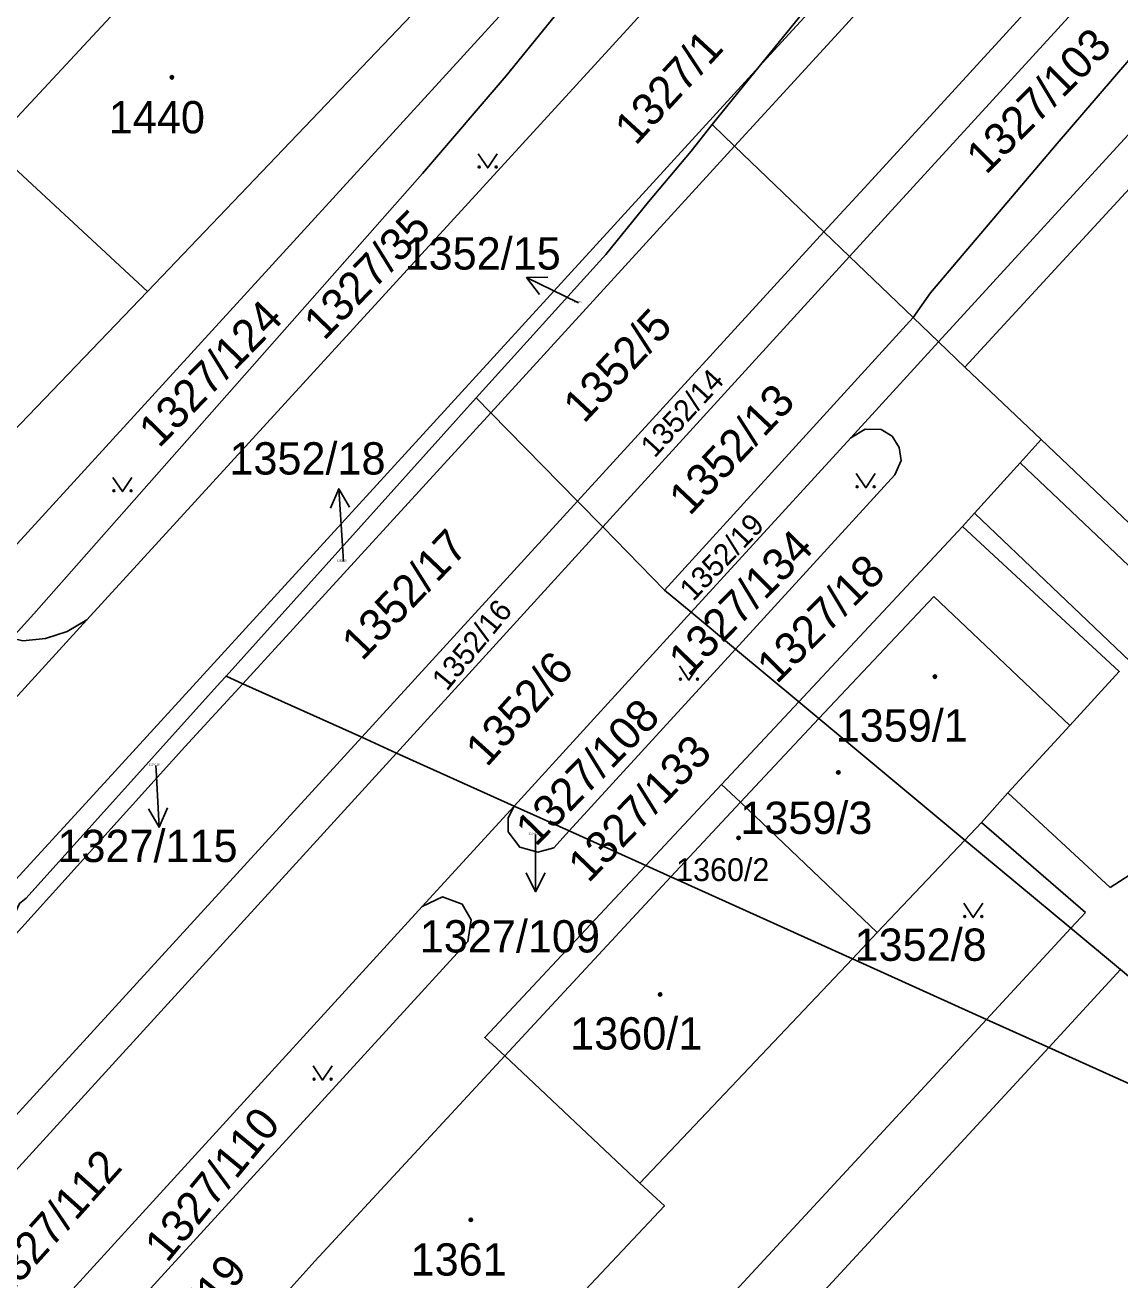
# Model space of a CAD drawing. Extents: x -598934 to -598196, y -1162208 to -1161502.
# Drawn here: x -598541.5 to -598483.9, y -1161724.5 to -1161658.4 of the extents above; entities that cross this region are included whole.
import ezdxf

# ---------------------------------------------------------------- set-up
doc = ezdxf.new("R2010")
doc.units = 0
for name, color, linetype in [('KN_CAR_KR', 7, 'Continuous'), ('KN_KULTURY', 7, 'Continuous'), ('KN_PARC_CIS_POM', 7, 'Continuous'), ('KN_PARC_CIS_POZ', 7, 'Continuous'), ('KN_PARC_CIS_STAV', 7, 'Continuous'), ('KN_PARC_PLOCHA', 7, 'Continuous'), ('PARC_C_SIPKA', 7, 'Continuous'), ('parcely_l', 7, 'Continuous')]:
    doc.layers.add(name, color=color, linetype=linetype)

msp = doc.modelspace()

# ---------------------------------------------------------------- linework, layer by layer
at = {"layer": 'KN_CAR_KR'}
for points in [[(-598489.16, -1161681.44), (-598464.99, -1161704.34)], [(-598491.55, -1161684.09), (-598483.38, -1161691.88)], [(-598499.74, -1161694.9), (-598493.7, -1161688.48)], [(-598493.7, -1161688.48), (-598486.54, -1161695.27)], [(-598503.87, -1161699.3), (-598499.74, -1161694.9)], [(-598503.87, -1161699.3), (-598507.53, -1161703.24)], [(-598484.42, -1161703.8), (-598489.8, -1161698.81)], [(-598491.18, -1161700.37), (-598485.72, -1161705.11)], [(-598507.53, -1161703.24), (-598516.27, -1161712.67)], [(-598484.42, -1161703.8), (-598482.89, -1161702.81)], [(-598485.72, -1161705.11), (-598486.49, -1161705.94)], [(-598486.49, -1161705.94), (-598490.92, -1161710.74)], [(-598487.64, -1161712.22), (-598483.87, -1161708.12)], [(-598490.92, -1161710.74), (-598521.91, -1161744.24)], [(-598499.66, -1161725.25), (-598487.64, -1161712.22)]]:
    msp.add_lwpolyline(points, dxfattribs=at)
at = {"layer": 'KN_KULTURY'}
for points in [[(-598517.672, -1161665.172), (-598517.172, -1161665.922), (-598516.672, -1161665.172)], [(-598536.892, -1161682.212), (-598536.392, -1161682.962), (-598535.892, -1161682.212)], [(-598497.782, -1161682.002), (-598497.282, -1161682.752), (-598496.782, -1161682.002)], [(-598507.082, -1161692.132), (-598506.582, -1161692.882), (-598506.082, -1161692.132)], [(-598492.122, -1161704.632), (-598491.622, -1161705.382), (-598491.122, -1161704.632)], [(-598526.362, -1161713.192), (-598525.862, -1161713.942), (-598525.362, -1161713.192)]]:
    msp.add_lwpolyline(points, dxfattribs=at)
for centre, radius in [((-598533.79, -1161661.15), 0.09), ((-598533.79, -1161661.15), 0.0398), ((-598517.622, -1161665.871), 0.05), ((-598516.723, -1161665.871), 0.05), ((-598536.842, -1161682.911), 0.05), ((-598535.943, -1161682.911), 0.05), ((-598497.732, -1161682.701), 0.05), ((-598496.833, -1161682.701), 0.05), ((-598507.032, -1161692.831), 0.05), ((-598506.133, -1161692.831), 0.05), ((-598493.64, -1161692.7), 0.09), ((-598493.64, -1161692.7), 0.0398), ((-598498.72, -1161697.74), 0.09), ((-598498.72, -1161697.74), 0.0398), ((-598503.97, -1161701.19), 0.09), ((-598503.97, -1161701.19), 0.0398), ((-598492.072, -1161705.331), 0.05), ((-598491.173, -1161705.331), 0.05), ((-598508.1, -1161709.43), 0.09), ((-598508.1, -1161709.43), 0.0398), ((-598526.312, -1161713.891), 0.05), ((-598525.413, -1161713.891), 0.05), ((-598518.06, -1161721.29), 0.09), ((-598518.06, -1161721.29), 0.0398)]:
    msp.add_circle(centre, radius, dxfattribs=at)
at = {"layer": 'KN_PARC_PLOCHA'}
for points in [[(-598601.64, -1161758.47), (-598594.41, -1161746.34), (-598574.71, -1161725.04), (-598562.49, -1161716.2), (-598546.26, -1161698.46), (-598538.27, -1161689.71), (-598508.71, -1161657.4), (-598500.6, -1161648.49), (-598493.91, -1161641.2), (-598488.42, -1161635.24), (-598481.9, -1161628.09), (-598472.12, -1161617.39), (-598454.81, -1161598.51), (-598446.33, -1161589.22), (-598435.01, -1161576.84), (-598438.32, -1161581.74), (-598452.8, -1161599.01), (-598453, -1161599.23), (-598502.88, -1161660.58), (-598537.16, -1161698.1), (-598569.06, -1161732.86), (-598601.28, -1161767.71)], [(-598444.82, -1161773.72), (-598474.53, -1161747.01), (-598458.77, -1161729.49), (-598468.63, -1161720.8), (-598458.45, -1161708.36), (-598488.05, -1161680.21), (-598492.06, -1161676.4), (-598438.63, -1161618.4)], [(-598510.61, -1161651.4), (-598544.94, -1161688.98), (-598543.81, -1161690.01), (-598542.71, -1161690.57), (-598542.22, -1161690.68), (-598545.81, -1161694.66), (-598546.28, -1161693.77), (-598547.91, -1161692.23), (-598565.2, -1161711.02), (-598575.32, -1161722.3), (-598575.72, -1161723.15), (-598605.82, -1161757.29)], [(-598600.45, -1161744.8), (-598587.23, -1161729.92), (-598586.27, -1161722.54), (-598585.47, -1161716.45), (-598581.89, -1161716.57), (-598581.96, -1161717.66), (-598579.95, -1161717.69), (-598579.94, -1161716.62), (-598578.57, -1161716.67), (-598576.31, -1161714.19), (-598575.54, -1161714.86), (-598573.24, -1161712.35), (-598573.97, -1161711.71), (-598571.95, -1161709.54), (-598560.12, -1161696.91), (-598552.08, -1161688.35), (-598548.99, -1161685.08), (-598548.07, -1161684.17), (-598547.19, -1161685.05), (-598535.07, -1161672.42), (-598520.79, -1161657.48)], [(-598538.31, -1161728.62), (-598518.22, -1161706.64), (-598518.05, -1161705.51), (-598518.51, -1161704.67), (-598519.56, -1161704.29), (-598520.62, -1161704.8), (-598515.78, -1161699.51), (-598516.09, -1161700.14), (-598516.1, -1161700.87), (-598515.49, -1161701.68), (-598514.54, -1161701.94), (-598513.69, -1161701.71), (-598512.88, -1161700.82), (-598508.86, -1161702.64), (-598510.5, -1161704.39), (-598517.33, -1161711.7), (-598516.27, -1161712.67), (-598526.27, -1161723.47), (-598528.95, -1161726.46)]]:
    msp.add_lwpolyline(points, dxfattribs=at)
for points in [[(-598449.39, -1161602.22), (-598457.13, -1161610.69), (-598502.88, -1161660.58), (-598453, -1161599.23), (-598452.8, -1161599.01)], [(-598447.76, -1161603.75), (-598454.84, -1161611.48), (-598455.16, -1161611.23), (-598501.41, -1161661.76), (-598504.18, -1161664.78), (-598505.37, -1161663.64), (-598502.88, -1161660.58), (-598457.13, -1161610.69), (-598449.39, -1161602.22)], [(-598443.61, -1161607.65), (-598450.63, -1161615.3), (-598450.33, -1161615.61), (-598497.15, -1161666.75), (-598499.48, -1161669.29), (-598504.18, -1161664.78), (-598501.41, -1161661.76), (-598455.16, -1161611.23), (-598454.84, -1161611.48), (-598447.76, -1161603.75)], [(-598441.98, -1161609.19), (-598452.99, -1161621.22), (-598496.1, -1161668.36), (-598498.13, -1161670.59), (-598499.48, -1161669.29), (-598497.15, -1161666.75), (-598450.33, -1161615.61), (-598450.63, -1161615.3), (-598443.61, -1161607.65)], [(-598440.63, -1161610.45), (-598487.2, -1161664.63), (-598493.87, -1161672.5), (-598494.79, -1161673.79), (-598498.13, -1161670.59), (-598496.1, -1161668.36), (-598452.99, -1161621.22), (-598441.98, -1161609.19)], [(-598437.32, -1161613.76), (-598448.19, -1161625.65), (-598493.45, -1161675.07), (-598494.79, -1161673.79), (-598493.87, -1161672.5), (-598487.2, -1161664.63), (-598440.63, -1161610.45), (-598440.23, -1161610.79), (-598438.3, -1161612.74)], [(-598435.81, -1161615.34), (-598438.63, -1161618.4), (-598492.06, -1161676.4), (-598493.45, -1161675.07), (-598448.19, -1161625.65), (-598437.32, -1161613.76)], [(-598509.32, -1161652.6), (-598516.2, -1161661.08), (-598520.6, -1161666.22), (-598541.05, -1161689.39), (-598542.22, -1161690.68), (-598542.71, -1161690.57), (-598543.81, -1161690.01), (-598544.94, -1161688.98), (-598510.61, -1161651.4)], [(-598508.71, -1161657.4), (-598538.27, -1161689.71), (-598539.31, -1161690.33), (-598540.45, -1161690.7), (-598541.63, -1161690.81), (-598542.22, -1161690.68), (-598541.05, -1161689.39), (-598520.6, -1161666.22), (-598516.2, -1161661.08), (-598509.32, -1161652.6), (-598508.82, -1161653.06), (-598508.32, -1161653.87), (-598508.03, -1161654.99), (-598508.15, -1161656.06)], [(-598520.79, -1161657.48), (-598535.07, -1161672.42), (-598543.36, -1161664.75), (-598536.1, -1161656.95), (-598533.57, -1161654.46), (-598530.26, -1161654.98), (-598526.88, -1161655.45), (-598523.54, -1161655.94)], [(-598536.1, -1161656.95), (-598543.36, -1161664.75), (-598548.22, -1161669.81), (-598553.01, -1161665.26), (-598553.29, -1161665.01), (-598553.46, -1161664.69), (-598553.52, -1161664.38), (-598553.45, -1161663.96), (-598553.24, -1161663.61), (-598552.96, -1161663.37), (-598548.13, -1161658.38), (-598545.02, -1161655.24), (-598536.87, -1161656.25)], [(-598505.37, -1161663.64), (-598506.47, -1161665.03), (-598508.71, -1161667.7), (-598510.96, -1161670.48), (-598517.78, -1161678.03), (-598530.94, -1161692.67), (-598531.26, -1161693.01), (-598541.47, -1161704.37), (-598541.81, -1161704.64), (-598543.16, -1161707.52), (-598568.17, -1161734.75), (-598580.79, -1161748.69), (-598599.26, -1161769.56), (-598615.93, -1161788.89), (-598618.28, -1161786.85), (-598601.28, -1161767.71), (-598569.06, -1161732.86), (-598537.16, -1161698.1), (-598502.88, -1161660.58)], [(-598504.18, -1161664.78), (-598517.01, -1161678.81), (-598517.78, -1161678.03), (-598510.96, -1161670.48), (-598508.71, -1161667.7), (-598506.47, -1161665.03), (-598505.37, -1161663.64)], [(-598535.07, -1161672.42), (-598547.19, -1161685.05), (-598548.07, -1161684.17), (-598555.37, -1161677.21), (-598550.02, -1161671.6), (-598548.22, -1161669.81), (-598543.36, -1161664.75)], [(-598499.48, -1161669.29), (-598512.45, -1161683.47), (-598517.01, -1161678.81), (-598504.18, -1161664.78)], [(-598498.13, -1161670.59), (-598511.12, -1161684.82), (-598512.45, -1161683.47), (-598499.48, -1161669.29)], [(-598494.79, -1161673.79), (-598507.87, -1161688.14), (-598511.12, -1161684.82), (-598498.13, -1161670.59)], [(-598493.45, -1161675.07), (-598498.07, -1161680.12), (-598506.46, -1161689.31), (-598507.87, -1161688.14), (-598494.79, -1161673.79)], [(-598492.06, -1161676.4), (-598488.05, -1161680.21), (-598489.16, -1161681.44), (-598491.55, -1161684.09), (-598492.18, -1161684.79), (-598500.8, -1161694.02), (-598504.13, -1161691.25), (-598495.74, -1161682.07), (-598495.42, -1161681.32), (-598495.52, -1161680.63), (-598495.89, -1161680.04), (-598496.47, -1161679.69), (-598497.31, -1161679.68), (-598498.07, -1161680.12), (-598493.45, -1161675.07)], [(-598517.01, -1161678.81), (-598530.06, -1161693.07), (-598530.94, -1161692.67), (-598517.78, -1161678.03)], [(-598512.45, -1161683.47), (-598523.8, -1161695.89), (-598530.06, -1161693.07), (-598517.01, -1161678.81)], [(-598504.13, -1161691.25), (-598506.46, -1161689.31), (-598498.07, -1161680.12), (-598497.31, -1161679.68), (-598496.47, -1161679.69), (-598495.89, -1161680.04), (-598495.52, -1161680.63), (-598495.42, -1161681.32), (-598495.74, -1161682.07)], [(-598468.63, -1161720.8), (-598471.86, -1161718.12), (-598473.6, -1161716.67), (-598483.87, -1161708.12), (-598486.49, -1161705.94), (-598492.06, -1161701.3), (-598491.18, -1161700.37), (-598489.8, -1161698.81), (-598486.54, -1161695.27), (-598483.94, -1161692.43), (-598492.18, -1161684.79), (-598491.55, -1161684.09), (-598489.16, -1161681.44), (-598488.05, -1161680.21), (-598458.45, -1161708.36)], [(-598511.12, -1161684.82), (-598521.97, -1161696.72), (-598523.8, -1161695.89), (-598512.45, -1161683.47)], [(-598507.87, -1161688.14), (-598506.46, -1161689.31), (-598515.78, -1161699.51), (-598521.97, -1161696.72), (-598511.12, -1161684.82)], [(-598492.06, -1161701.3), (-598499.74, -1161694.9), (-598500.8, -1161694.02), (-598492.18, -1161684.79), (-598483.94, -1161692.43), (-598486.54, -1161695.27), (-598489.8, -1161698.81), (-598491.18, -1161700.37)], [(-598504.13, -1161691.25), (-598512.88, -1161700.82), (-598515.78, -1161699.51), (-598506.46, -1161689.31)], [(-598546.26, -1161698.46), (-598545.63, -1161697.5), (-598545.35, -1161696.46), (-598545.49, -1161695.27), (-598545.81, -1161694.66), (-598542.22, -1161690.68), (-598541.63, -1161690.81), (-598540.45, -1161690.7), (-598539.31, -1161690.33), (-598538.27, -1161689.71)], [(-598500.8, -1161694.02), (-598504.87, -1161698.37), (-598508.86, -1161702.64), (-598512.88, -1161700.82), (-598504.13, -1161691.25)], [(-598530.06, -1161693.07), (-598533.11, -1161696.4), (-598543.16, -1161707.52), (-598541.81, -1161704.64), (-598541.47, -1161704.37), (-598531.26, -1161693.01), (-598530.94, -1161692.67)], [(-598523.8, -1161695.89), (-598544.3, -1161718.3), (-598568.94, -1161745.33), (-598571.83, -1161742.74), (-598572.86, -1161741.8), (-598567.54, -1161735.78), (-598565.39, -1161733.07), (-598543.16, -1161707.52), (-598533.11, -1161696.4), (-598530.06, -1161693.07)], [(-598492.06, -1161701.3), (-598496.67, -1161706.17), (-598503.87, -1161699.3), (-598504.87, -1161698.37), (-598500.8, -1161694.02), (-598499.74, -1161694.9)], [(-598521.97, -1161696.72), (-598547.88, -1161725.12), (-598567, -1161747.08), (-598568.94, -1161745.33), (-598544.3, -1161718.3), (-598523.8, -1161695.89)], [(-598515.78, -1161699.51), (-598520.62, -1161704.8), (-598540.3, -1161726.37), (-598545.62, -1161732.34), (-598551.22, -1161738.78), (-598552.06, -1161740.1), (-598557.21, -1161749.89), (-598557.79, -1161750.75), (-598560.03, -1161753.34), (-598567, -1161747.08), (-598547.88, -1161725.12), (-598521.97, -1161696.72)], [(-598496.67, -1161706.17), (-598497.98, -1161707.55), (-598507.53, -1161703.24), (-598508.86, -1161702.64), (-598504.87, -1161698.37), (-598503.87, -1161699.3)], [(-598512.88, -1161700.82), (-598513.69, -1161701.71), (-598514.54, -1161701.94), (-598515.49, -1161701.68), (-598516.1, -1161700.87), (-598516.09, -1161700.14), (-598515.78, -1161699.51)], [(-598468.63, -1161720.8), (-598472.67, -1161718.98), (-598474.84, -1161718), (-598487.64, -1161712.22), (-598490.92, -1161710.74), (-598497.98, -1161707.55), (-598496.67, -1161706.17), (-598492.06, -1161701.3), (-598486.49, -1161705.94), (-598483.87, -1161708.12), (-598473.6, -1161716.67), (-598471.86, -1161718.12)], [(-598497.98, -1161707.55), (-598509.16, -1161719.36), (-598516.27, -1161712.67), (-598517.33, -1161711.7), (-598510.5, -1161704.39), (-598508.86, -1161702.64), (-598507.53, -1161703.24)], [(-598540.3, -1161726.37), (-598520.62, -1161704.8), (-598519.56, -1161704.29), (-598518.51, -1161704.67), (-598518.05, -1161705.51), (-598518.22, -1161706.64), (-598538.31, -1161728.62), (-598539.25, -1161728.86), (-598540.1, -1161728.5), (-598540.65, -1161727.46)], [(-598468.63, -1161720.8), (-598458.77, -1161729.49), (-598474.53, -1161747.01), (-598505.54, -1161780.43), (-598505.91, -1161780.84), (-598507.88, -1161780.28), (-598515.19, -1161778.23), (-598542.18, -1161767.07), (-598540.95, -1161765.46), (-598543.04, -1161763.56), (-598545.78, -1161761.07), (-598536.13, -1161750.75), (-598533.19, -1161747.65), (-598527.64, -1161741.82), (-598526.22, -1161740.28), (-598520.88, -1161734.41), (-598507.87, -1161720.56), (-598509.16, -1161719.36), (-598497.98, -1161707.55), (-598490.92, -1161710.74), (-598487.64, -1161712.22), (-598474.84, -1161718), (-598472.67, -1161718.98)], [(-598509.16, -1161719.36), (-598507.87, -1161720.56), (-598520.88, -1161734.41), (-598528.95, -1161726.46), (-598526.27, -1161723.47), (-598516.27, -1161712.67)]]:
    msp.add_lwpolyline(points, close=True, dxfattribs=at)
at = {"layer": 'PARC_C_SIPKA'}
for points in [[(-598514.448, -1161672.576), (-598515.129, -1161671.69), (-598514.011, -1161671.677)], [(-598512.39, -1161673.02), (-598512.43, -1161673), (-598515.129, -1161671.69)], [(-598525.449, -1161683.837), (-598525.015, -1161682.806), (-598524.451, -1161683.772)], [(-598524.77, -1161686.64), (-598524.82, -1161685.8), (-598525.015, -1161682.806)], [(-598534.63, -1161697.38), (-598534.62, -1161697.63), (-598534.467, -1161700.626)], [(-598534.019, -1161699.602), (-598534.467, -1161700.626), (-598535.017, -1161699.653)], [(-598514.65, -1161701.01), (-598514.65, -1161701.02), (-598514.65, -1161704.02)], [(-598514.15, -1161703.02), (-598514.65, -1161704.02), (-598515.15, -1161703.02)]]:
    msp.add_lwpolyline(points, dxfattribs=at)
at = {"layer": 'parcely_l'}
for points in [[(-598502.88, -1161660.58), (-598453, -1161599.23), (-598452.8, -1161599.01)], [(-598449.39, -1161602.22), (-598457.13, -1161610.69), (-598502.88, -1161660.58)], [(-598504.18, -1161664.78), (-598501.41, -1161661.76), (-598455.16, -1161611.23), (-598454.84, -1161611.48), (-598447.76, -1161603.75)], [(-598443.61, -1161607.65), (-598450.63, -1161615.3), (-598450.33, -1161615.61), (-598497.15, -1161666.75), (-598499.48, -1161669.29)], [(-598498.13, -1161670.59), (-598496.1, -1161668.36), (-598452.99, -1161621.22), (-598441.98, -1161609.19)], [(-598440.63, -1161610.45), (-598487.2, -1161664.63), (-598493.87, -1161672.5), (-598494.79, -1161673.79)], [(-598493.45, -1161675.07), (-598448.19, -1161625.65), (-598437.32, -1161613.76)], [(-598435.81, -1161615.34), (-598438.63, -1161618.4), (-598492.06, -1161676.4)], [(-598510.61, -1161651.4), (-598544.94, -1161688.98), (-598543.81, -1161690.01), (-598542.71, -1161690.57), (-598542.22, -1161690.68)], [(-598542.22, -1161690.68), (-598541.05, -1161689.39), (-598520.6, -1161666.22), (-598516.2, -1161661.08), (-598509.32, -1161652.6)], [(-598543.36, -1161664.75), (-598536.1, -1161656.95)], [(-598508.71, -1161657.4), (-598538.27, -1161689.71)], [(-598520.79, -1161657.48), (-598535.07, -1161672.42)], [(-598618.28, -1161786.85), (-598601.28, -1161767.71), (-598569.06, -1161732.86), (-598537.16, -1161698.1), (-598502.88, -1161660.58)], [(-598502.88, -1161660.58), (-598505.37, -1161663.64)], [(-598517.78, -1161678.03), (-598510.96, -1161670.48), (-598508.71, -1161667.7), (-598506.47, -1161665.03), (-598505.37, -1161663.64)], [(-598505.37, -1161663.64), (-598504.18, -1161664.78)], [(-598543.36, -1161664.75), (-598535.07, -1161672.42)], [(-598504.18, -1161664.78), (-598517.01, -1161678.81)], [(-598504.18, -1161664.78), (-598499.48, -1161669.29)], [(-598499.48, -1161669.29), (-598512.45, -1161683.47)], [(-598499.48, -1161669.29), (-598498.13, -1161670.59)], [(-598511.12, -1161684.82), (-598498.13, -1161670.59)], [(-598494.79, -1161673.79), (-598498.13, -1161670.59)], [(-598535.07, -1161672.42), (-598547.19, -1161685.05), (-598548.07, -1161684.17)], [(-598494.79, -1161673.79), (-598507.87, -1161688.14)], [(-598493.45, -1161675.07), (-598494.79, -1161673.79)], [(-598493.45, -1161675.07), (-598498.07, -1161680.12)], [(-598492.06, -1161676.4), (-598493.45, -1161675.07)], [(-598492.06, -1161676.4), (-598488.05, -1161680.21)], [(-598530.94, -1161692.67), (-598517.78, -1161678.03)], [(-598517.78, -1161678.03), (-598517.01, -1161678.81)], [(-598517.01, -1161678.81), (-598530.06, -1161693.07)], [(-598512.45, -1161683.47), (-598517.01, -1161678.81)], [(-598498.07, -1161680.12), (-598506.46, -1161689.31)], [(-598498.07, -1161680.12), (-598497.31, -1161679.68), (-598496.47, -1161679.69), (-598495.89, -1161680.04), (-598495.52, -1161680.63), (-598495.42, -1161681.32), (-598495.74, -1161682.07), (-598504.13, -1161691.25)], [(-598492.18, -1161684.79), (-598491.55, -1161684.09), (-598489.16, -1161681.44), (-598488.05, -1161680.21)], [(-598488.05, -1161680.21), (-598458.45, -1161708.36), (-598468.63, -1161720.8)], [(-598512.45, -1161683.47), (-598523.8, -1161695.89)], [(-598512.45, -1161683.47), (-598511.12, -1161684.82)], [(-598511.12, -1161684.82), (-598521.97, -1161696.72)], [(-598507.87, -1161688.14), (-598511.12, -1161684.82)], [(-598500.8, -1161694.02), (-598492.18, -1161684.79)], [(-598492.06, -1161701.3), (-598491.18, -1161700.37), (-598489.8, -1161698.81), (-598486.54, -1161695.27), (-598483.94, -1161692.43), (-598492.18, -1161684.79)], [(-598506.46, -1161689.31), (-598507.87, -1161688.14)], [(-598515.78, -1161699.51), (-598506.46, -1161689.31)], [(-598506.46, -1161689.31), (-598504.13, -1161691.25)], [(-598538.27, -1161689.71), (-598546.26, -1161698.46)], [(-598538.27, -1161689.71), (-598539.31, -1161690.33), (-598540.45, -1161690.7), (-598541.63, -1161690.81), (-598542.22, -1161690.68)], [(-598504.13, -1161691.25), (-598512.88, -1161700.82)], [(-598504.13, -1161691.25), (-598500.8, -1161694.02)], [(-598530.94, -1161692.67), (-598531.26, -1161693.01), (-598541.47, -1161704.37), (-598541.81, -1161704.64), (-598543.16, -1161707.52)], [(-598530.06, -1161693.07), (-598530.94, -1161692.67)], [(-598530.06, -1161693.07), (-598533.11, -1161696.4), (-598543.16, -1161707.52)], [(-598523.8, -1161695.89), (-598530.06, -1161693.07)], [(-598504.87, -1161698.37), (-598500.8, -1161694.02)], [(-598500.8, -1161694.02), (-598499.74, -1161694.9), (-598492.06, -1161701.3)], [(-598523.8, -1161695.89), (-598544.3, -1161718.3), (-598568.94, -1161745.33)], [(-598521.97, -1161696.72), (-598523.8, -1161695.89)], [(-598521.97, -1161696.72), (-598547.88, -1161725.12), (-598567, -1161747.08)], [(-598515.78, -1161699.51), (-598521.97, -1161696.72)], [(-598508.86, -1161702.64), (-598504.87, -1161698.37)], [(-598496.67, -1161706.17), (-598503.87, -1161699.3), (-598504.87, -1161698.37)], [(-598520.62, -1161704.8), (-598515.78, -1161699.51)], [(-598512.88, -1161700.82), (-598513.69, -1161701.71), (-598514.54, -1161701.94), (-598515.49, -1161701.68), (-598516.1, -1161700.87), (-598516.09, -1161700.14), (-598515.78, -1161699.51)], [(-598512.88, -1161700.82), (-598515.78, -1161699.51)], [(-598508.86, -1161702.64), (-598512.88, -1161700.82)], [(-598492.06, -1161701.3), (-598496.67, -1161706.17)], [(-598468.63, -1161720.8), (-598471.86, -1161718.12), (-598473.6, -1161716.67), (-598483.87, -1161708.12), (-598486.49, -1161705.94), (-598492.06, -1161701.3)], [(-598516.27, -1161712.67), (-598517.33, -1161711.7), (-598510.5, -1161704.39), (-598508.86, -1161702.64)], [(-598508.86, -1161702.64), (-598507.53, -1161703.24), (-598497.98, -1161707.55)], [(-598520.62, -1161704.8), (-598519.56, -1161704.29), (-598518.51, -1161704.67), (-598518.05, -1161705.51), (-598518.22, -1161706.64), (-598538.31, -1161728.62), (-598539.25, -1161728.86), (-598540.1, -1161728.5), (-598540.65, -1161727.46), (-598540.3, -1161726.37)], [(-598540.3, -1161726.37), (-598520.62, -1161704.8)], [(-598496.67, -1161706.17), (-598497.98, -1161707.55)], [(-598497.98, -1161707.55), (-598509.16, -1161719.36)], [(-598468.63, -1161720.8), (-598472.67, -1161718.98), (-598474.84, -1161718), (-598487.64, -1161712.22), (-598490.92, -1161710.74), (-598497.98, -1161707.55)], [(-598528.95, -1161726.46), (-598526.27, -1161723.47), (-598516.27, -1161712.67)], [(-598516.27, -1161712.67), (-598509.16, -1161719.36)], [(-598509.16, -1161719.36), (-598507.87, -1161720.56), (-598520.88, -1161734.41)]]:
    msp.add_lwpolyline(points, dxfattribs=at)

# ---------------------------------------------------------------- texts
at = {"layer": 'KN_PARC_CIS_POM'}
for s, p in [('1352/15', (-598512.723, -1161673.02)), ('1352/18', (-598525.103, -1161686.64)), ('1327/115', (-598535.013, -1161697.38)), ('1327/109', (-598515.033, -1161701.01))]:
    msp.add_text(s, height=0.1, dxfattribs=at).set_placement(p)
at = {"layer": 'KN_PARC_CIS_POZ'}
for s, height, rotation, p in [('1327/1', 1.7, 47.45863, (-598509.387, -1161664.789)), ('1327/103', 1.7, 45.02502, (-598490.946, -1161666.32)), ('1327/35', 1.7, 45.87432, (-598525.785, -1161675.058)), ('1327/124', 1.7, 45.73165, (-598534.469, -1161680.716)), ('1352/5', 1.7, 47.0293, (-598512.105, -1161679.418)), ('1352/14', 1.14, 47.44174, (-598508.39, -1161681.229)), ('1352/13', 1.7, 46.69165, (-598506.547, -1161684.283)), ('1352/19', 1.14, 46.19926, (-598506.359, -1161688.773)), ('1352/17', 1.7, 46.37287, (-598523.78, -1161691.922)), ('1327/134', 1.7, 45.29969, (-598506.602, -1161692.765)), ('1327/18', 1.7, 45, (-598501.963, -1161693.133)), ('1352/16', 1.14, 50.55884, (-598519.324, -1161693.505)), ('1352/6', 1.7, 47.87692, (-598517.22, -1161697.511)), ('1327/108', 1.7, 45.70067, (-598514.641, -1161701.694)), ('1327/133', 1.7, 45.9998, (-598511.875, -1161703.612)), ('1327/110', 1.7, 50.50168, (-598534.045, -1161723.608)), ('1327/112', 1.7, 48.09007, (-598542.663, -1161725.63)), ('1327/19', 1.7, 51.13446, (-598534.919, -1161730.406))]:
    msp.add_text(s, height=height, rotation=rotation, dxfattribs=at).set_placement(p)
for s, p in [('1352/15', (-598521.547, -1161671.27)), ('1352/18', (-598530.767, -1161682.06)), ('1327/115', (-598539.817, -1161702.46)), ('1327/109', (-598520.747, -1161707.22)), ('1352/8', (-598497.867, -1161707.66))]:
    msp.add_text(s, height=1.7, dxfattribs=at).set_placement(p)
at = {"layer": 'KN_PARC_CIS_STAV'}
for s, height, p in [('1440', 1.7, (-598537.112, -1161664.1)), ('1359/1', 1.7, (-598498.862, -1161696.12)), ('1359/3', 1.7, (-598503.882, -1161700.98)), ('1360/2', 1.2, (-598507.26, -1161703.46)), ('1360/1', 1.7, (-598512.832, -1161712.33)), ('1361', 1.7, (-598521.232, -1161724.23))]:
    msp.add_text(s, height=height, dxfattribs=at).set_placement(p)

doc.saveas('drawing.dxf')
